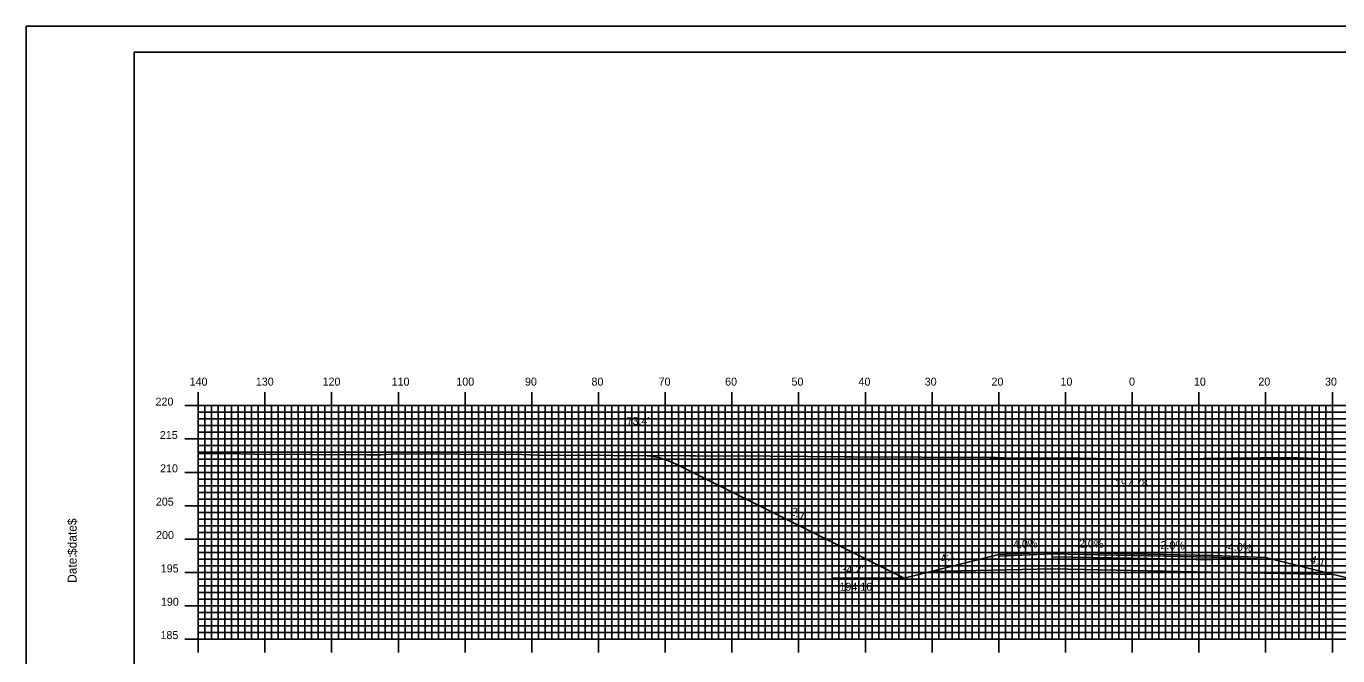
# Model space of a CAD drawing. Extents: x 1799962 to 1800305, y 442591 to 442811.
# Drawn here: x 1799961.7 to 1800158.3, y 442716.2 to 442810.5 of the extents above; entities that cross this region are included whole.
import ezdxf

# ---------------------------------------------------------------- set-up
doc = ezdxf.new("R2010")
doc.units = 0
for name, color, linetype in [('ANNOTATION', 7, 'Continuous'), ('BORDER', 7, 'Continuous'), ('D_Roadway_Centerline', 7, 'Continuous'), ('D_Roadway_Centerline_Text', 7, 'Continuous'), ('D_Roadway_Edge_Shoulder', 7, 'Continuous'), ('D_Roadway_Edge_TW', 7, 'Continuous'), ('D_Roadway_Pavement', 7, 'Continuous'), ('D_Roadway_SlopeLines', 7, 'Continuous'), ('D_Roadway_SubGrade', 7, 'Continuous'), ('D_Text_Standard', 7, 'Continuous'), ('H_V ANNOTATION', 7, 'Continuous'), ('MAJOR', 7, 'Continuous'), ('MINOR', 7, 'Continuous'), ('PDRAIN', 7, 'Continuous'), ('PLOT BOUNDARY', 7, 'Continuous'), ('S_Roadway_Centerline', 7, 'Continuous')]:
    doc.layers.add(name, color=color, linetype=linetype)

msp = doc.modelspace()

# ---------------------------------------------------------------- linework, layer by layer
at = {"layer": 'BORDER'}
msp.add_lwpolyline([(1799977.92, 442596.67), (1800297.92, 442596.67), (1800297.92, 442806.67), (1799977.92, 442806.67)], close=True, dxfattribs=at)
at = {"layer": 'D_Roadway_Centerline'}
msp.add_lwpolyline([(1800054.16, 442746.18), (1800055.41, 442746.1), (1800056.66, 442745.86), (1800057.91, 442745.47), (1800059.16, 442744.92), (1800093.35, 442727.83), (1800097.35, 442728.83), (1800107.52, 442731.37), (1800115.52, 442731.69), (1800127.52, 442731.45), (1800139.52, 442731.21), (1800147.52, 442730.89), (1800157.7, 442728.35), (1800161.7, 442727.35), (1800196.04, 442744.51), (1800197.29, 442745.07), (1800198.54, 442745.47), (1800199.79, 442745.72), (1800201.04, 442745.83)], dxfattribs=at)
at = {"layer": 'D_Roadway_Edge_Shoulder'}
for points in [[(1800115.52, 442731.69), (1800107.52, 442731.37), (1800107.52, 442731.12), (1800115.52, 442731.44)], [(1800139.52, 442731.21), (1800147.52, 442730.89), (1800147.52, 442730.64), (1800139.52, 442730.96)]]:
    msp.add_lwpolyline(points, close=True, dxfattribs=at)
at = {"layer": 'D_Roadway_Edge_TW'}
msp.add_lwpolyline([(1800115.52, 442731.44), (1800115.52, 442731.69), (1800127.52, 442731.45), (1800139.52, 442731.21), (1800139.52, 442730.96), (1800127.52, 442731.2)], close=True, dxfattribs=at)
at = {"layer": 'D_Roadway_Pavement'}
msp.add_lwpolyline([(1800115.52, 442731.02), (1800115.52, 442731.44), (1800127.52, 442731.2), (1800139.52, 442730.96), (1800139.52, 442730.54), (1800127.52, 442730.78)], close=True, dxfattribs=at)
at = {"layer": 'D_Roadway_SlopeLines'}
for points in [[(1800093.35, 442727.83), (1800059.16, 442744.92), (1800057.91, 442745.47), (1800056.66, 442745.86), (1800055.41, 442746.1), (1800054.16, 442746.18)], [(1800107.52, 442731.37), (1800093.35, 442727.83)], [(1800147.52, 442730.89), (1800161.7, 442727.35)]]:
    msp.add_lwpolyline(points, dxfattribs=at)
at = {"layer": 'D_Roadway_SubGrade'}
msp.add_lwpolyline([(1800115.52, 442729.19), (1800097.35, 442728.83), (1800107.52, 442731.37), (1800107.52, 442731.12), (1800115.52, 442731.44), (1800127.52, 442731.2), (1800139.52, 442730.96), (1800147.52, 442730.64), (1800147.52, 442730.89), (1800157.7, 442728.35), (1800139.52, 442728.71), (1800127.52, 442728.95)], close=True, dxfattribs=at)
at = {"layer": 'MAJOR'}
for p, q in [((1799987.52, 442755.67), (1799987.52, 442753.67)), ((1799997.52, 442755.67), (1799997.52, 442753.67)), ((1800007.52, 442755.67), (1800007.52, 442753.67)), ((1800017.52, 442755.67), (1800017.52, 442753.67)), ((1800027.52, 442755.67), (1800027.52, 442753.67)), ((1800037.52, 442755.67), (1800037.52, 442753.67)), ((1800047.52, 442755.67), (1800047.52, 442753.67)), ((1800057.52, 442755.67), (1800057.52, 442753.67)), ((1800067.52, 442755.67), (1800067.52, 442753.67)), ((1800077.52, 442755.67), (1800077.52, 442753.67)), ((1800087.52, 442755.67), (1800087.52, 442753.67)), ((1800097.52, 442755.67), (1800097.52, 442753.67)), ((1800107.52, 442755.67), (1800107.52, 442753.67)), ((1800117.52, 442755.67), (1800117.52, 442753.67)), ((1800127.52, 442755.67), (1800127.52, 442753.67)), ((1800137.52, 442755.67), (1800137.52, 442753.67)), ((1800147.52, 442755.67), (1800147.52, 442753.67)), ((1800157.52, 442755.67), (1800157.52, 442753.67)), ((1799985.52, 442753.67), (1799987.52, 442753.67)), ((1799987.52, 442753.67), (1800267.52, 442753.67)), ((1799987.52, 442718.67), (1799987.52, 442753.67)), ((1799987.52, 442718.67), (1799987.52, 442753.67)), ((1799987.52, 442753.67), (1800267.52, 442753.67)), ((1799997.52, 442718.67), (1799997.52, 442753.67)), ((1800007.52, 442718.67), (1800007.52, 442753.67)), ((1800017.52, 442718.67), (1800017.52, 442753.67)), ((1800027.52, 442718.67), (1800027.52, 442753.67)), ((1800037.52, 442718.67), (1800037.52, 442753.67)), ((1800047.52, 442718.67), (1800047.52, 442753.67)), ((1800057.52, 442718.67), (1800057.52, 442753.67)), ((1800067.52, 442718.67), (1800067.52, 442753.67)), ((1800077.52, 442718.67), (1800077.52, 442753.67)), ((1800087.52, 442718.67), (1800087.52, 442753.67)), ((1800097.52, 442718.67), (1800097.52, 442753.67)), ((1800107.52, 442718.67), (1800107.52, 442753.67)), ((1800117.52, 442718.67), (1800117.52, 442753.67)), ((1800127.52, 442718.67), (1800127.52, 442753.67)), ((1800137.52, 442718.67), (1800137.52, 442753.67)), ((1800147.52, 442718.67), (1800147.52, 442753.67)), ((1800157.52, 442718.67), (1800157.52, 442753.67)), ((1799985.52, 442748.67), (1799987.52, 442748.67)), ((1799987.52, 442748.67), (1800267.52, 442748.67)), ((1799985.52, 442743.67), (1799987.52, 442743.67)), ((1799987.52, 442743.67), (1800267.52, 442743.67)), ((1799985.52, 442738.67), (1799987.52, 442738.67)), ((1799987.52, 442738.67), (1800267.52, 442738.67)), ((1799985.52, 442733.67), (1799987.52, 442733.67)), ((1799987.52, 442733.67), (1800267.52, 442733.67)), ((1799985.52, 442728.67), (1799987.52, 442728.67)), ((1799987.52, 442728.67), (1800267.52, 442728.67)), ((1799985.52, 442723.67), (1799987.52, 442723.67)), ((1799987.52, 442723.67), (1800267.52, 442723.67)), ((1799985.52, 442718.67), (1799987.52, 442718.67)), ((1799987.52, 442718.67), (1800267.52, 442718.67)), ((1799987.52, 442718.67), (1800267.52, 442718.67)), ((1799987.52, 442716.66), (1799987.52, 442718.67)), ((1799997.52, 442716.66), (1799997.52, 442718.67)), ((1800007.52, 442716.66), (1800007.52, 442718.67)), ((1800017.52, 442716.66), (1800017.52, 442718.67)), ((1800027.52, 442716.66), (1800027.52, 442718.67)), ((1800037.52, 442716.66), (1800037.52, 442718.67)), ((1800047.52, 442716.66), (1800047.52, 442718.67)), ((1800057.52, 442716.66), (1800057.52, 442718.67)), ((1800067.52, 442716.66), (1800067.52, 442718.67)), ((1800077.52, 442716.66), (1800077.52, 442718.67)), ((1800087.52, 442716.66), (1800087.52, 442718.67)), ((1800097.52, 442716.66), (1800097.52, 442718.67)), ((1800107.52, 442716.66), (1800107.52, 442718.67)), ((1800117.52, 442716.66), (1800117.52, 442718.67)), ((1800127.52, 442716.66), (1800127.52, 442718.67)), ((1800137.52, 442716.66), (1800137.52, 442718.67)), ((1800147.52, 442716.66), (1800147.52, 442718.67)), ((1800157.52, 442716.66), (1800157.52, 442718.67))]:
    msp.add_line(p, q, dxfattribs=at)
at = {"layer": 'MINOR'}
for p, q in [((1799988.52, 442718.67), (1799988.52, 442753.67)), ((1799989.52, 442718.67), (1799989.52, 442753.67)), ((1799990.52, 442718.67), (1799990.52, 442753.67)), ((1799991.52, 442718.67), (1799991.52, 442753.67)), ((1799992.52, 442718.67), (1799992.52, 442753.67)), ((1799993.52, 442718.67), (1799993.52, 442753.67)), ((1799994.52, 442718.67), (1799994.52, 442753.67)), ((1799995.52, 442718.67), (1799995.52, 442753.67)), ((1799996.52, 442718.67), (1799996.52, 442753.67)), ((1799998.52, 442718.67), (1799998.52, 442753.67)), ((1799999.52, 442718.67), (1799999.52, 442753.67)), ((1800000.52, 442718.67), (1800000.52, 442753.67)), ((1800001.52, 442718.67), (1800001.52, 442753.67)), ((1800002.52, 442718.67), (1800002.52, 442753.67)), ((1800003.52, 442718.67), (1800003.52, 442753.67)), ((1800004.52, 442718.67), (1800004.52, 442753.67)), ((1800005.52, 442718.67), (1800005.52, 442753.67)), ((1800006.52, 442718.67), (1800006.52, 442753.67)), ((1800008.52, 442718.67), (1800008.52, 442753.67)), ((1800009.52, 442718.67), (1800009.52, 442753.67)), ((1800010.52, 442718.67), (1800010.52, 442753.67)), ((1800011.52, 442718.67), (1800011.52, 442753.67)), ((1800012.52, 442718.67), (1800012.52, 442753.67)), ((1800013.52, 442718.67), (1800013.52, 442753.67)), ((1800014.52, 442718.67), (1800014.52, 442753.67)), ((1800015.52, 442718.67), (1800015.52, 442753.67)), ((1800016.52, 442718.67), (1800016.52, 442753.67)), ((1800018.52, 442718.67), (1800018.52, 442753.67)), ((1800019.52, 442718.67), (1800019.52, 442753.67)), ((1800020.52, 442718.67), (1800020.52, 442753.67)), ((1800021.52, 442718.67), (1800021.52, 442753.67)), ((1800022.52, 442718.67), (1800022.52, 442753.67)), ((1800023.52, 442718.67), (1800023.52, 442753.67)), ((1800024.52, 442718.67), (1800024.52, 442753.67)), ((1800025.52, 442718.67), (1800025.52, 442753.67)), ((1800026.52, 442718.67), (1800026.52, 442753.67)), ((1800028.52, 442718.67), (1800028.52, 442753.67)), ((1800029.52, 442718.67), (1800029.52, 442753.67)), ((1800030.52, 442718.67), (1800030.52, 442753.67)), ((1800031.52, 442718.67), (1800031.52, 442753.67)), ((1800032.52, 442718.67), (1800032.52, 442753.67)), ((1800033.52, 442718.67), (1800033.52, 442753.67)), ((1800034.52, 442718.67), (1800034.52, 442753.67)), ((1800035.52, 442718.67), (1800035.52, 442753.67)), ((1800036.52, 442718.67), (1800036.52, 442753.67)), ((1800038.52, 442718.67), (1800038.52, 442753.67)), ((1800039.52, 442718.67), (1800039.52, 442753.67)), ((1800040.52, 442718.67), (1800040.52, 442753.67)), ((1800041.52, 442718.67), (1800041.52, 442753.67)), ((1800042.52, 442718.67), (1800042.52, 442753.67)), ((1800043.52, 442718.67), (1800043.52, 442753.67)), ((1800044.52, 442718.67), (1800044.52, 442753.67)), ((1800045.52, 442718.67), (1800045.52, 442753.67)), ((1800046.52, 442718.67), (1800046.52, 442753.67)), ((1800048.52, 442718.67), (1800048.52, 442753.67)), ((1800049.52, 442718.67), (1800049.52, 442753.67)), ((1800050.52, 442718.67), (1800050.52, 442753.67)), ((1800051.52, 442718.67), (1800051.52, 442753.67)), ((1800052.52, 442718.67), (1800052.52, 442753.67)), ((1800053.52, 442718.67), (1800053.52, 442753.67)), ((1800054.52, 442718.67), (1800054.52, 442753.67)), ((1800055.52, 442718.67), (1800055.52, 442753.67)), ((1800056.52, 442718.67), (1800056.52, 442753.67)), ((1800058.52, 442718.67), (1800058.52, 442753.67)), ((1800059.52, 442718.67), (1800059.52, 442753.67)), ((1800060.52, 442718.67), (1800060.52, 442753.67)), ((1800061.52, 442718.67), (1800061.52, 442753.67)), ((1800062.52, 442718.67), (1800062.52, 442753.67)), ((1800063.52, 442718.67), (1800063.52, 442753.67)), ((1800064.52, 442718.67), (1800064.52, 442753.67)), ((1800065.52, 442718.67), (1800065.52, 442753.67)), ((1800066.52, 442718.67), (1800066.52, 442753.67)), ((1800068.52, 442718.67), (1800068.52, 442753.67)), ((1800069.52, 442718.67), (1800069.52, 442753.67)), ((1800070.52, 442718.67), (1800070.52, 442753.67)), ((1800071.52, 442718.67), (1800071.52, 442753.67)), ((1800072.52, 442718.67), (1800072.52, 442753.67)), ((1800073.52, 442718.67), (1800073.52, 442753.67)), ((1800074.52, 442718.67), (1800074.52, 442753.67)), ((1800075.52, 442718.67), (1800075.52, 442753.67)), ((1800076.52, 442718.67), (1800076.52, 442753.67)), ((1800078.52, 442718.67), (1800078.52, 442753.67)), ((1800079.52, 442718.67), (1800079.52, 442753.67)), ((1800080.52, 442718.67), (1800080.52, 442753.67)), ((1800081.52, 442718.67), (1800081.52, 442753.67)), ((1800082.52, 442718.67), (1800082.52, 442753.67)), ((1800083.52, 442718.67), (1800083.52, 442753.67)), ((1800084.52, 442718.67), (1800084.52, 442753.67)), ((1800085.52, 442718.67), (1800085.52, 442753.67)), ((1800086.52, 442718.67), (1800086.52, 442753.67)), ((1800088.52, 442718.67), (1800088.52, 442753.67)), ((1800089.52, 442718.67), (1800089.52, 442753.67)), ((1800090.52, 442718.67), (1800090.52, 442753.67)), ((1800091.52, 442718.67), (1800091.52, 442753.67)), ((1800092.52, 442718.67), (1800092.52, 442753.67)), ((1800093.52, 442718.67), (1800093.52, 442753.67)), ((1800094.52, 442718.67), (1800094.52, 442753.67)), ((1800095.52, 442718.67), (1800095.52, 442753.67)), ((1800096.52, 442718.67), (1800096.52, 442753.67)), ((1800098.52, 442718.67), (1800098.52, 442753.67)), ((1800099.52, 442718.67), (1800099.52, 442753.67)), ((1800100.52, 442718.67), (1800100.52, 442753.67)), ((1800101.52, 442718.67), (1800101.52, 442753.67)), ((1800102.52, 442718.67), (1800102.52, 442753.67)), ((1800103.52, 442718.67), (1800103.52, 442753.67)), ((1800104.52, 442718.67), (1800104.52, 442753.67)), ((1800105.52, 442718.67), (1800105.52, 442753.67)), ((1800106.52, 442718.67), (1800106.52, 442753.67)), ((1800108.52, 442718.67), (1800108.52, 442753.67)), ((1800109.52, 442718.67), (1800109.52, 442753.67)), ((1800110.52, 442718.67), (1800110.52, 442753.67)), ((1800111.52, 442718.67), (1800111.52, 442753.67)), ((1800112.52, 442718.67), (1800112.52, 442753.67)), ((1800113.52, 442718.67), (1800113.52, 442753.67)), ((1800114.52, 442718.67), (1800114.52, 442753.67)), ((1800115.52, 442718.67), (1800115.52, 442753.67)), ((1800116.52, 442718.67), (1800116.52, 442753.67)), ((1800118.52, 442718.67), (1800118.52, 442753.67)), ((1800119.52, 442718.67), (1800119.52, 442753.67)), ((1800120.52, 442718.67), (1800120.52, 442753.67)), ((1800121.52, 442718.67), (1800121.52, 442753.67)), ((1800122.52, 442718.67), (1800122.52, 442753.67)), ((1800123.52, 442718.67), (1800123.52, 442753.67)), ((1800124.52, 442718.67), (1800124.52, 442753.67)), ((1800125.52, 442718.67), (1800125.52, 442753.67)), ((1800126.52, 442718.67), (1800126.52, 442753.67)), ((1800128.52, 442718.67), (1800128.52, 442753.67)), ((1800129.52, 442718.67), (1800129.52, 442753.67)), ((1800130.52, 442718.67), (1800130.52, 442753.67)), ((1800131.52, 442718.67), (1800131.52, 442753.67)), ((1800132.52, 442718.67), (1800132.52, 442753.67)), ((1800133.52, 442718.67), (1800133.52, 442753.67)), ((1800134.52, 442718.67), (1800134.52, 442753.67)), ((1800135.52, 442718.67), (1800135.52, 442753.67)), ((1800136.52, 442718.67), (1800136.52, 442753.67)), ((1800138.52, 442718.67), (1800138.52, 442753.67)), ((1800139.52, 442718.67), (1800139.52, 442753.67)), ((1800140.52, 442718.67), (1800140.52, 442753.67)), ((1800141.52, 442718.67), (1800141.52, 442753.67)), ((1800142.52, 442718.67), (1800142.52, 442753.67)), ((1800143.52, 442718.67), (1800143.52, 442753.67)), ((1800144.52, 442718.67), (1800144.52, 442753.67)), ((1800145.52, 442718.67), (1800145.52, 442753.67)), ((1800146.52, 442718.67), (1800146.52, 442753.67)), ((1800148.52, 442718.67), (1800148.52, 442753.67)), ((1800149.52, 442718.67), (1800149.52, 442753.67)), ((1800150.52, 442718.67), (1800150.52, 442753.67)), ((1800151.52, 442718.67), (1800151.52, 442753.67)), ((1800152.52, 442718.67), (1800152.52, 442753.67)), ((1800153.52, 442718.67), (1800153.52, 442753.67)), ((1800154.52, 442718.67), (1800154.52, 442753.67)), ((1800155.52, 442718.67), (1800155.52, 442753.67)), ((1800156.52, 442718.67), (1800156.52, 442753.67)), ((1799987.52, 442752.67), (1800267.52, 442752.67)), ((1799987.52, 442752.67), (1799989.53, 442752.67)), ((1799987.52, 442751.67), (1800267.52, 442751.67)), ((1799987.52, 442751.67), (1799989.53, 442751.67)), ((1799987.52, 442750.67), (1800267.52, 442750.67)), ((1799987.52, 442750.67), (1799989.53, 442750.67)), ((1799987.52, 442749.67), (1800267.52, 442749.67)), ((1799987.52, 442749.67), (1799989.53, 442749.67)), ((1799987.52, 442747.67), (1800267.52, 442747.67)), ((1799987.52, 442747.67), (1799989.53, 442747.67)), ((1799987.52, 442746.67), (1800267.52, 442746.67)), ((1799987.52, 442746.67), (1799989.53, 442746.67)), ((1799987.52, 442745.67), (1800267.52, 442745.67)), ((1799987.52, 442745.67), (1799989.53, 442745.67)), ((1799987.52, 442744.67), (1800267.52, 442744.67)), ((1799987.52, 442744.67), (1799989.53, 442744.67)), ((1799987.52, 442742.67), (1800267.52, 442742.67)), ((1799987.52, 442742.67), (1799989.53, 442742.67)), ((1799987.52, 442741.67), (1800267.52, 442741.67)), ((1799987.52, 442741.67), (1799989.53, 442741.67)), ((1799987.52, 442740.67), (1800267.52, 442740.67)), ((1799987.52, 442740.67), (1799989.53, 442740.67)), ((1799987.52, 442739.67), (1800267.52, 442739.67)), ((1799987.52, 442739.67), (1799989.53, 442739.67)), ((1799987.52, 442737.67), (1800267.52, 442737.67)), ((1799987.52, 442737.67), (1799989.53, 442737.67)), ((1799987.52, 442736.67), (1800267.52, 442736.67)), ((1799987.52, 442736.67), (1799989.53, 442736.67)), ((1799987.52, 442735.67), (1800267.52, 442735.67)), ((1799987.52, 442735.67), (1799989.53, 442735.67)), ((1799987.52, 442734.67), (1800267.52, 442734.67)), ((1799987.52, 442734.67), (1799989.53, 442734.67)), ((1799987.52, 442732.67), (1800267.52, 442732.67)), ((1799987.52, 442732.67), (1799989.53, 442732.67)), ((1799987.52, 442731.67), (1800267.52, 442731.67)), ((1799987.52, 442731.67), (1799989.53, 442731.67)), ((1799987.52, 442730.67), (1800267.52, 442730.67)), ((1799987.52, 442730.67), (1799989.53, 442730.67)), ((1799987.52, 442729.67), (1800267.52, 442729.67)), ((1799987.52, 442729.67), (1799989.53, 442729.67)), ((1799987.52, 442727.67), (1800267.52, 442727.67)), ((1799987.52, 442727.67), (1799989.53, 442727.67)), ((1799987.52, 442726.67), (1800267.52, 442726.67)), ((1799987.52, 442726.67), (1799989.53, 442726.67)), ((1799987.52, 442725.67), (1800267.52, 442725.67)), ((1799987.52, 442725.67), (1799989.53, 442725.67)), ((1799987.52, 442724.67), (1800267.52, 442724.67)), ((1799987.52, 442724.67), (1799989.53, 442724.67)), ((1799987.52, 442722.67), (1800267.52, 442722.67)), ((1799987.52, 442722.67), (1799989.53, 442722.67)), ((1799987.52, 442721.67), (1800267.52, 442721.67)), ((1799987.52, 442721.67), (1799989.53, 442721.67)), ((1799987.52, 442720.67), (1800267.52, 442720.67)), ((1799987.52, 442720.67), (1799989.53, 442720.67)), ((1799987.52, 442719.67), (1800267.52, 442719.67)), ((1799987.52, 442719.67), (1799989.53, 442719.67))]:
    msp.add_line(p, q, dxfattribs=at)
at = {"layer": 'PDRAIN'}
msp.add_line((1800082.63, 442727.83), (1800093.35, 442727.83), dxfattribs=at)
at = {"layer": 'PLOT BOUNDARY'}
msp.add_lwpolyline([(1799961.74, 442590.55), (1800301.74, 442590.55), (1800301.74, 442810.55), (1799961.74, 442810.55)], close=True, dxfattribs=at)
at = {"layer": 'S_Roadway_Centerline'}
msp.add_lwpolyline([(1799987.52, 442746.47), (1799987.65, 442746.47), (1799991.83, 442746.48), (1799995.93, 442746.4), (1800012.84, 442746.31), (1800014.95, 442746.3), (1800017.18, 442746.44), (1800036.04, 442746.34), (1800038.31, 442746.25), (1800061.16, 442746.15), (1800062.04, 442746.14), (1800073.23, 442746.07), (1800084.56, 442745.98), (1800084.62, 442745.98), (1800084.67, 442745.98), (1800085.67, 442745.98), (1800106.23, 442745.9), (1800107.11, 442745.89), (1800108.29, 442745.87), (1800119.72, 442745.79), (1800129.3, 442745.59), (1800133.93, 442745.68), (1800151.14, 442745.88), (1800158, 442745.66), (1800165.91, 442745.54)], dxfattribs=at)

# ---------------------------------------------------------------- texts
at = {"layer": 'ANNOTATION'}
for s, rotation, p in [('2:1', 333.4349, (1800076.19, 442737.44)), ('-4.0%', 2.2906, (1800109.15, 442732.24)), ('2.0%', 358.8542, (1800119.53, 442732.41)), ('-2.0%', 358.8542, (1800131.21, 442732.18)), ('4:1', 14.0362, (1800098.97, 442730.09)), ('-4.0%', 357.7094, (1800141.31, 442731.94)), ('4:1', 345.9638, (1800154.12, 442730.1))]:
    msp.add_text(s, height=1.2, rotation=rotation, dxfattribs=at).set_placement(p)
for s, p in [("34.2'", (1800083.79, 442728.52)), ('194.16', (1800083.64, 442725.92))]:
    msp.add_text(s, height=1.2, dxfattribs=at).set_placement(p)
at = {"layer": 'BORDER'}
for s, p in [('$date$', (1799969.29, 442731.28)), ('Date:', (1799969.29, 442727.1))]:
    msp.add_text(s, height=1.339, rotation=90, dxfattribs=at).set_placement(p)
at = {"layer": 'D_Roadway_Centerline'}
for s, p in [('C', (1800127.52, 442731.45)), ('L', (1800127.52, 442731.44))]:
    msp.add_text(s, height=0.0146, dxfattribs=at).set_placement(p)
at = {"layer": 'D_Roadway_Centerline_Text'}
msp.add_text('197.78', height=1.2, dxfattribs=at).set_placement((1800124.94, 442741.48))
at = {"layer": 'D_Text_Standard'}
msp.add_text("73.4'", height=1.2, dxfattribs=at).set_placement((1800051.73, 442750.78))
at = {"layer": 'H_V ANNOTATION'}
for s, p in [('140', (1799986.23, 442756.67)), ('130', (1799996.15, 442756.67)), ('120', (1800006.16, 442756.67)), ('110', (1800016.51, 442756.67)), ('100', (1800026.21, 442756.67)), ('90', (1800036.5, 442756.67)), ('80', (1800046.47, 442756.67)), ('70', (1800056.53, 442756.67)), ('60', (1800066.5, 442756.67)), ('50', (1800076.45, 442756.67)), ('40', (1800086.5, 442756.67)), ('30', (1800096.42, 442756.67)), ('20', (1800106.43, 442756.67)), ('10', (1800116.77, 442756.67)), ('0', (1800127.04, 442756.67)), ('10', (1800136.77, 442756.67)), ('20', (1800146.43, 442756.67)), ('30', (1800156.42, 442756.67)), ('220', (1799981.12, 442753.67)), ('215', (1799981.77, 442748.67)), ('210', (1799981.8, 442743.67)), ('205', (1799981.17, 442738.67)), ('200', (1799981.2, 442733.67)), ('195', (1799981.9, 442728.67)), ('190', (1799981.93, 442723.67)), ('185', (1799981.86, 442718.67))]:
    msp.add_text(s, height=1.2, dxfattribs=at).set_placement(p)
at = {"layer": 'MAJOR'}
msp.add_text('-', height=0.012, dxfattribs=at).set_placement((1799987.51, 442718.67))

doc.saveas('drawing.dxf')
